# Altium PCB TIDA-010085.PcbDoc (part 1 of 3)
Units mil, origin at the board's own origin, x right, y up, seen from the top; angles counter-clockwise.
Board outline 1968.5 x 2559.06 mil, 4 copper layers (Top Layer, Signal Layer 1, Signal Layer 2, Bottom Layer), stack 5.6 mil thick; 254 components, 133 nets, 771 pads, 156 vias.
Unrouted connection lines stored in the file: 2.
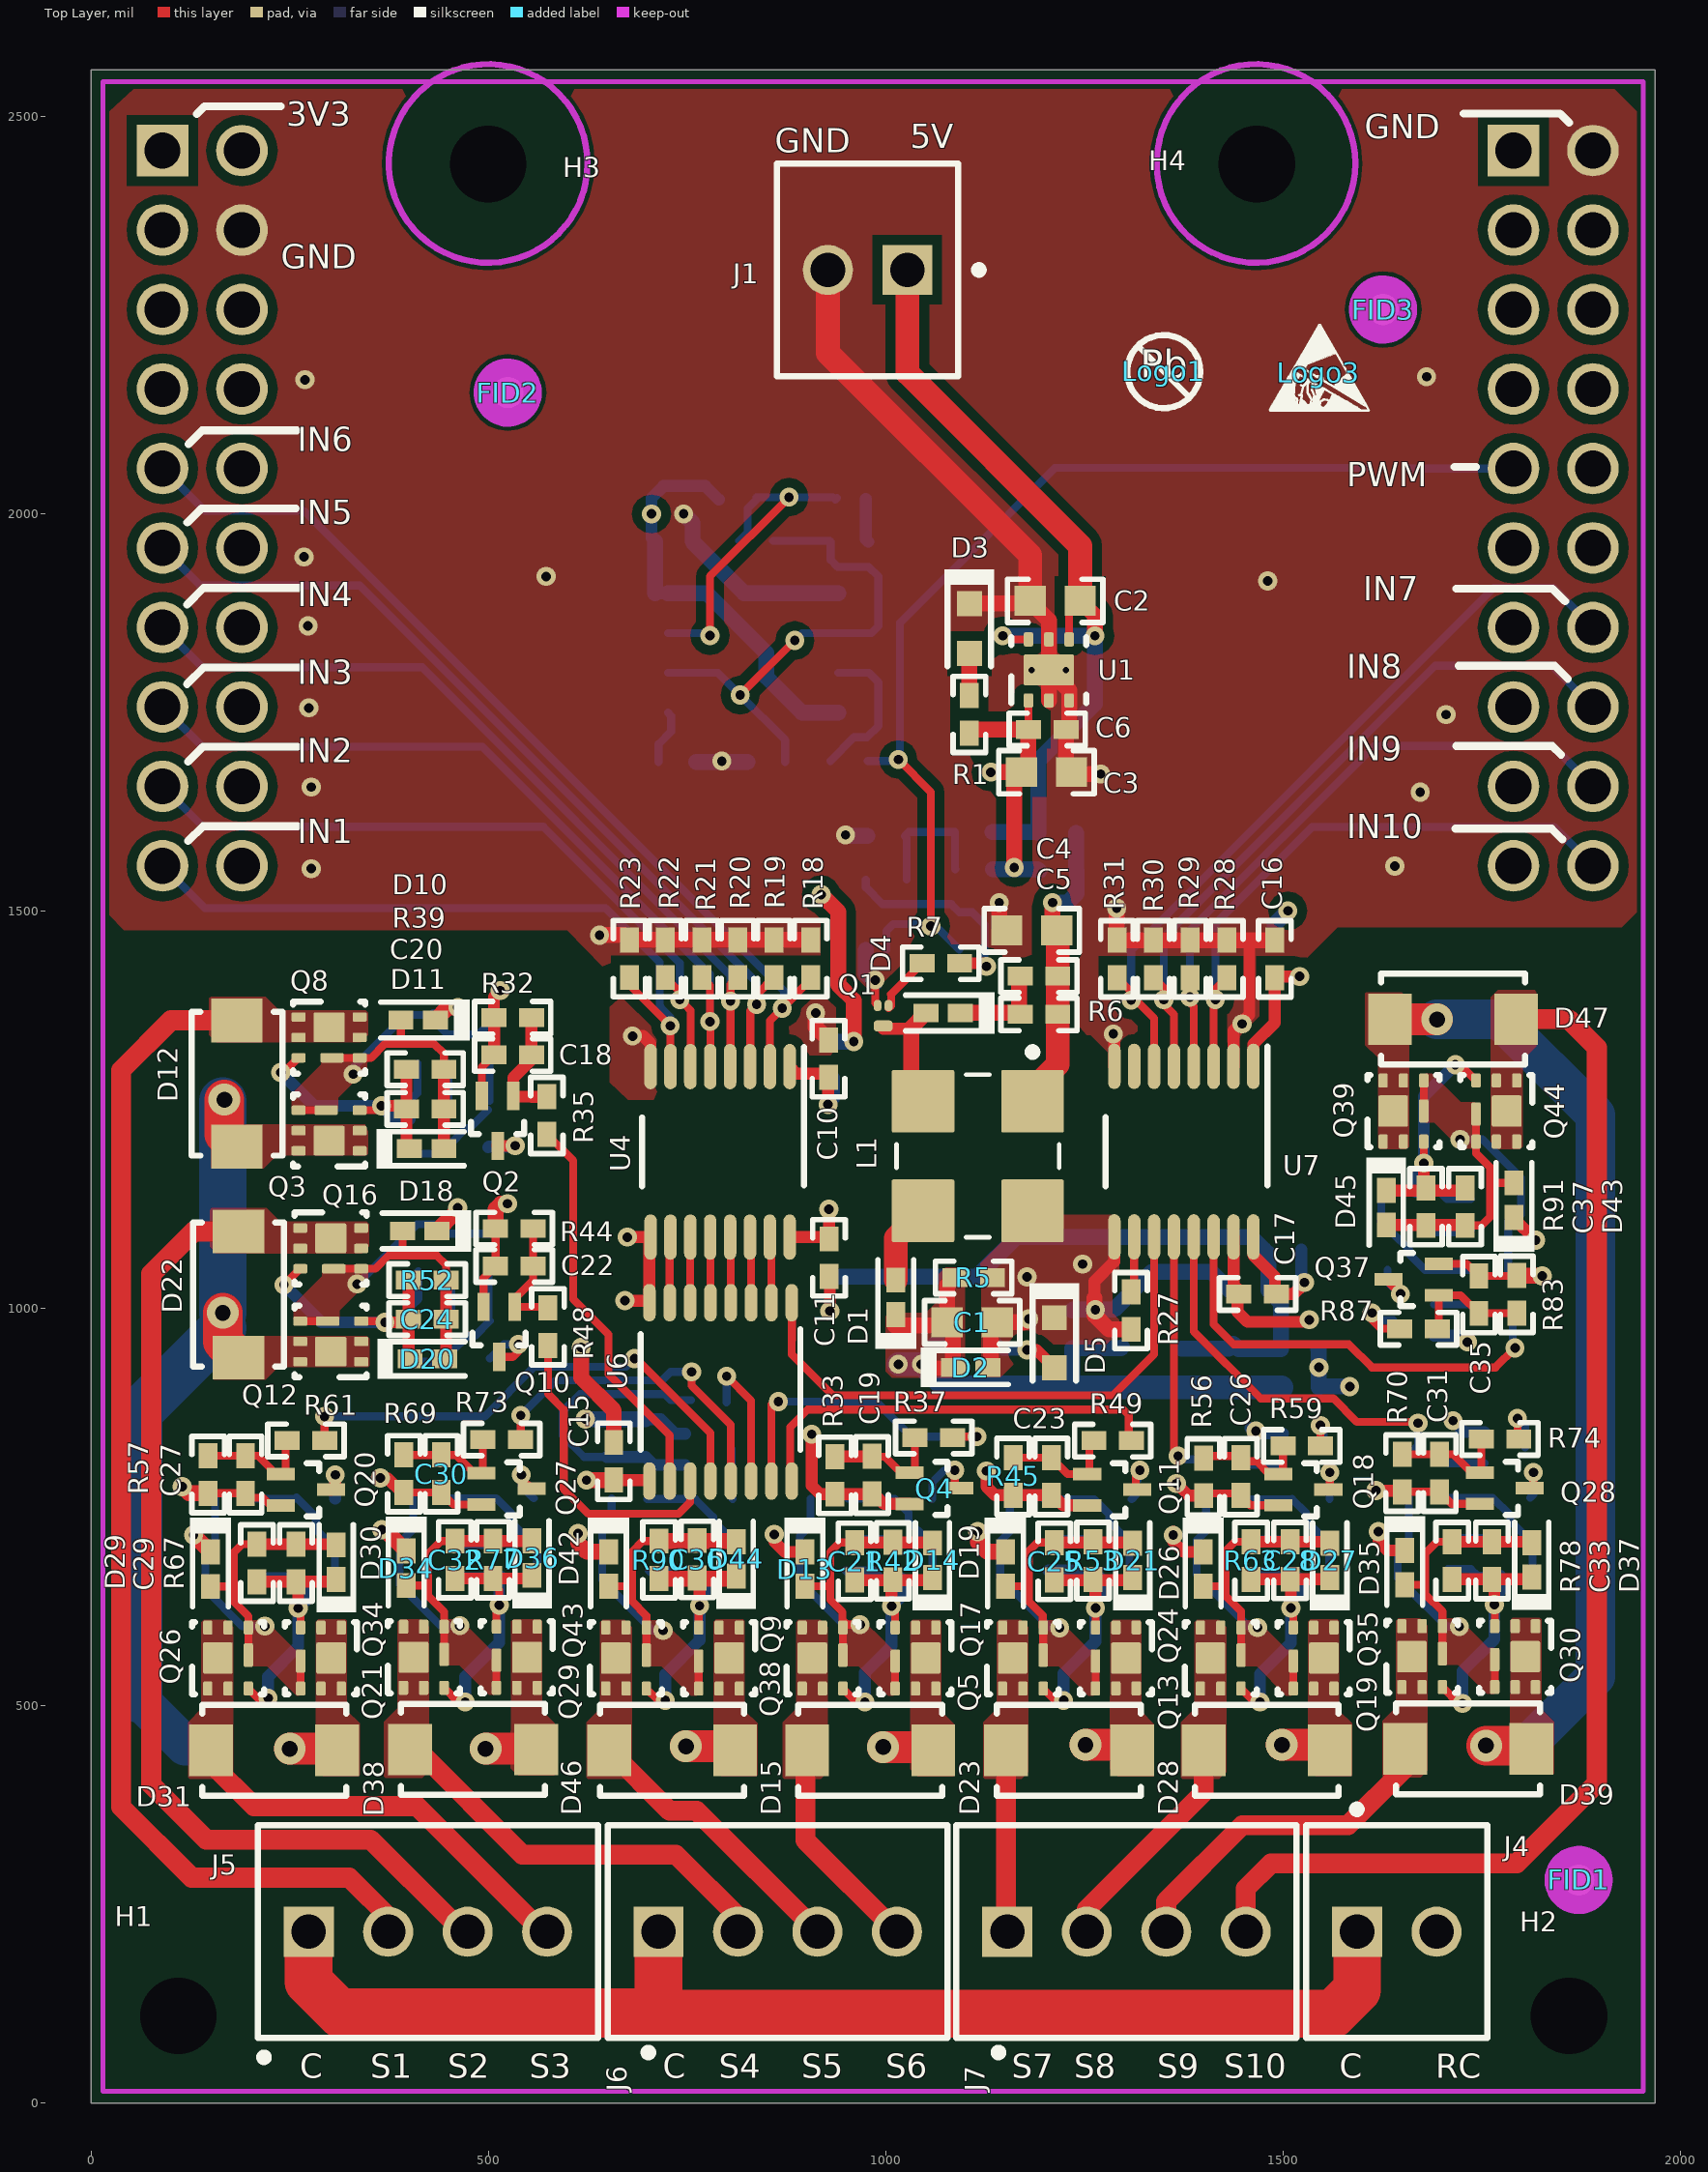
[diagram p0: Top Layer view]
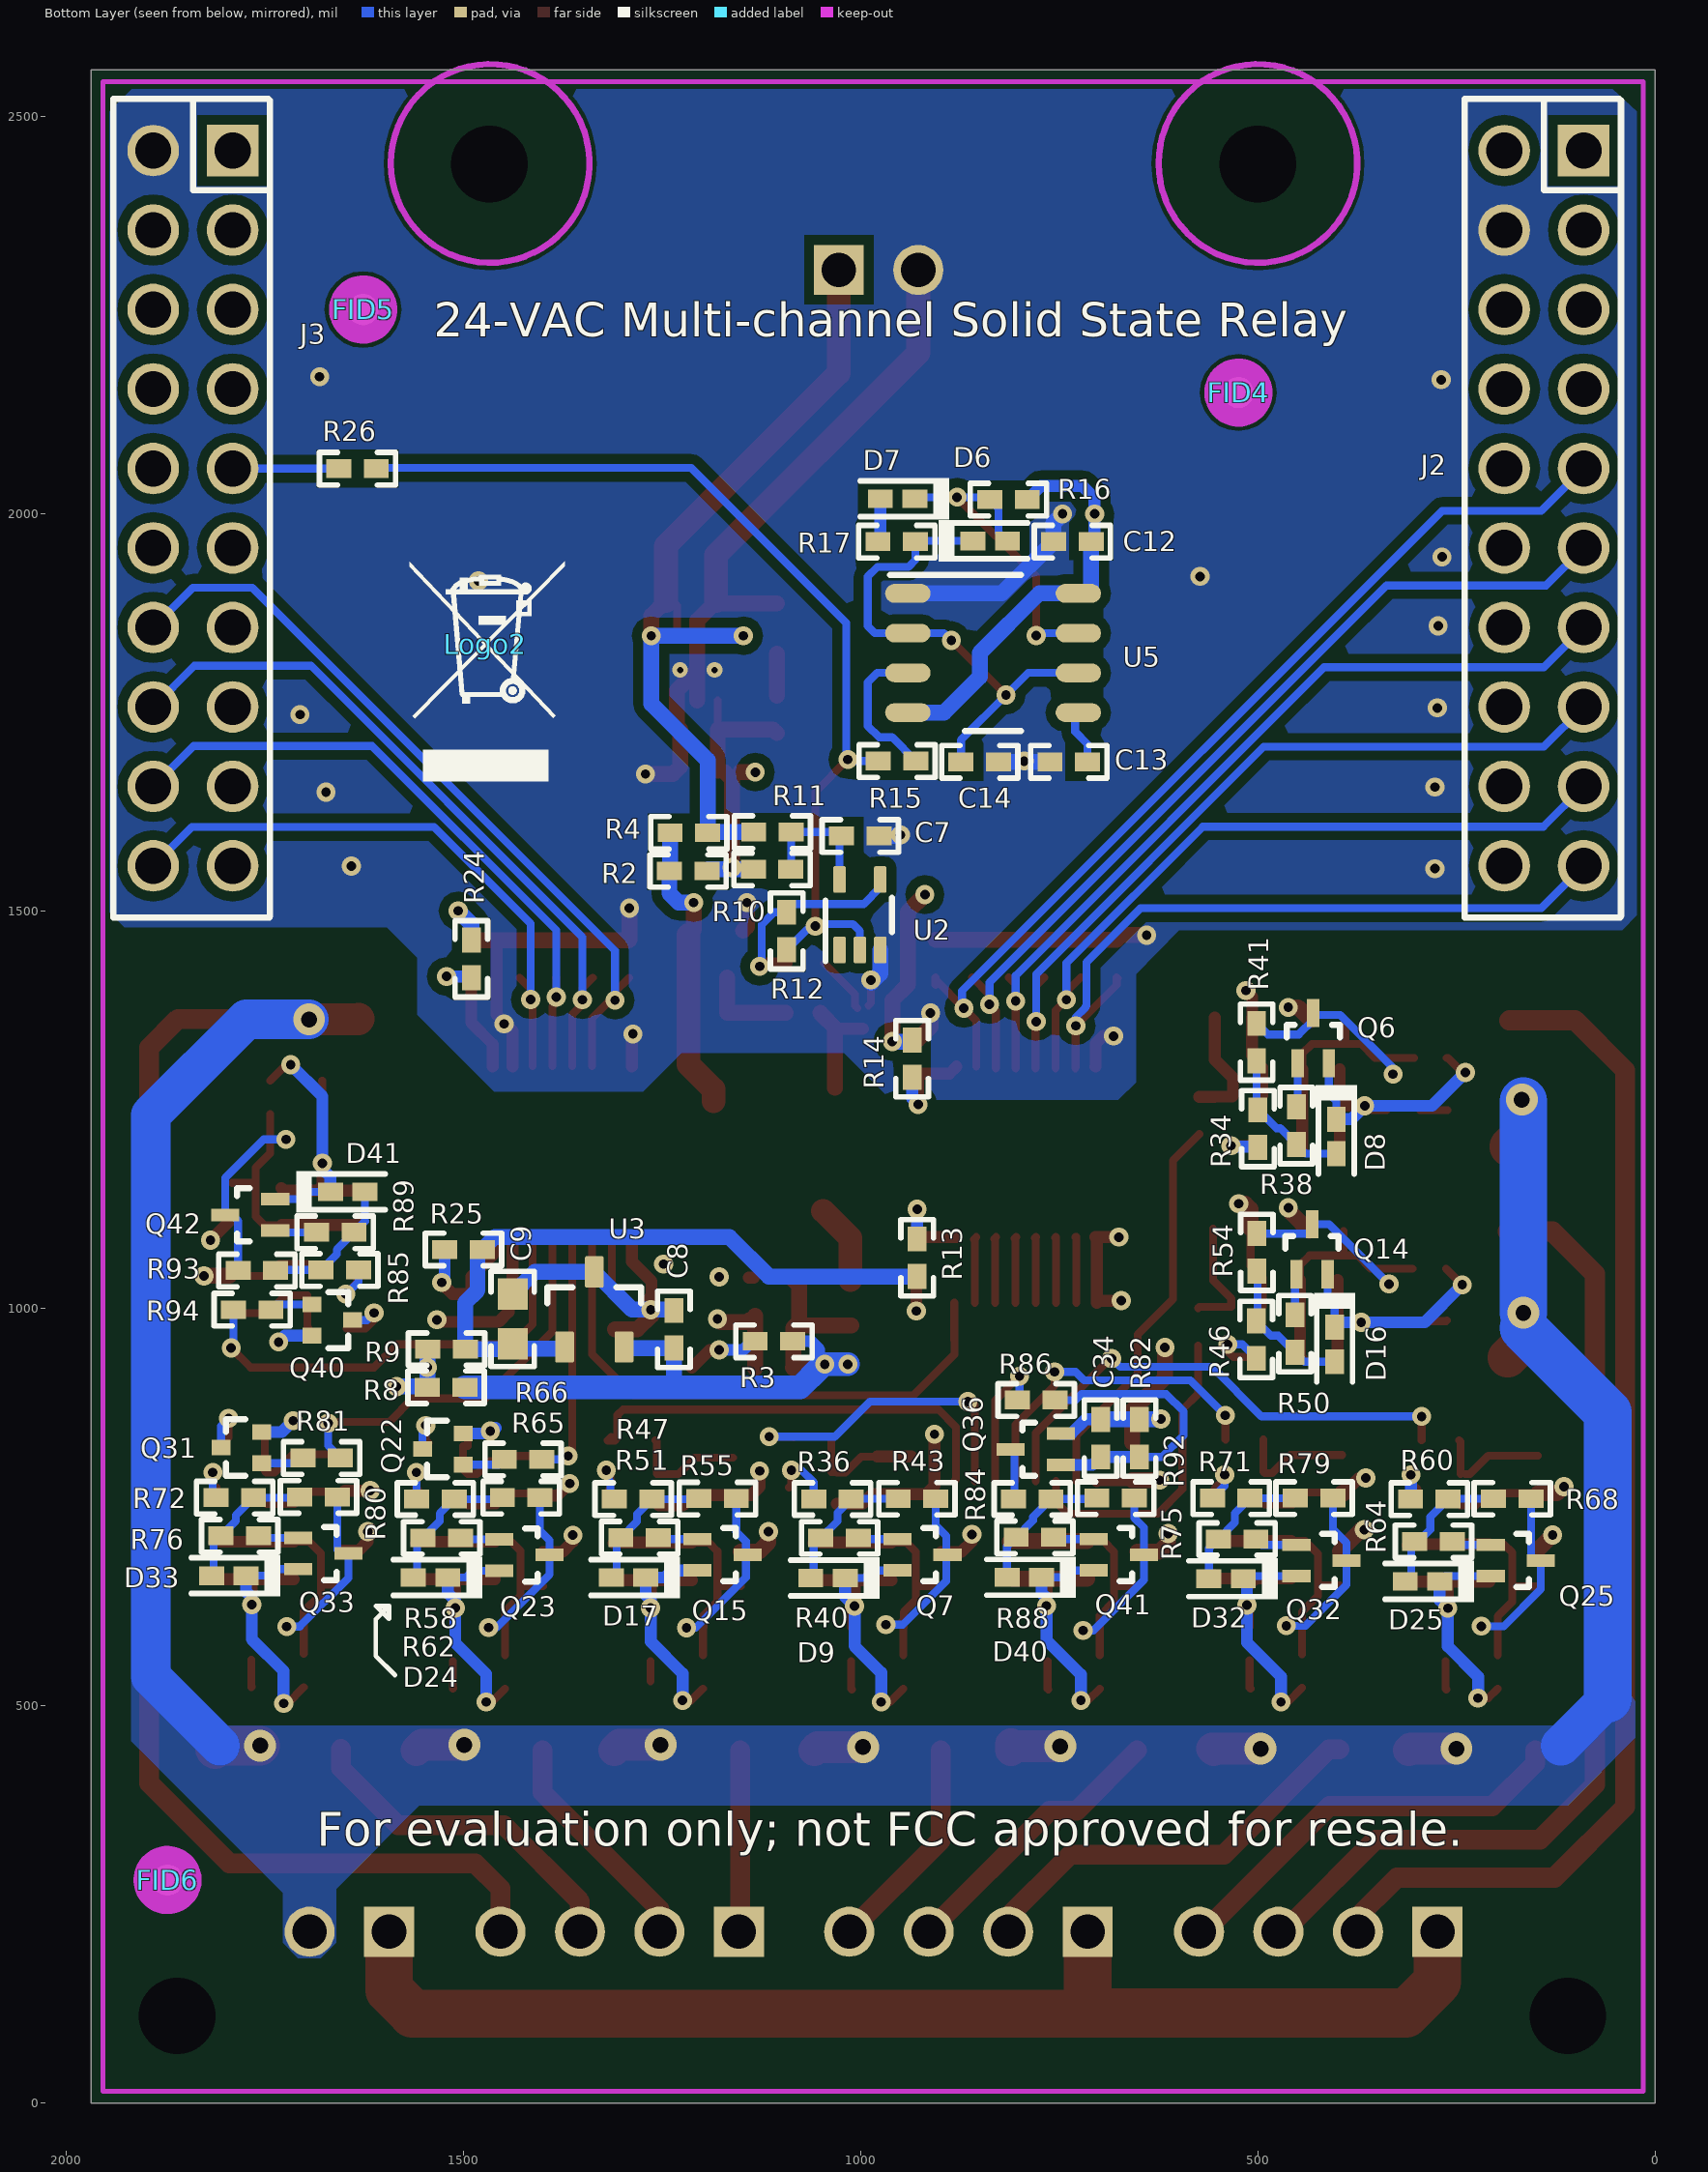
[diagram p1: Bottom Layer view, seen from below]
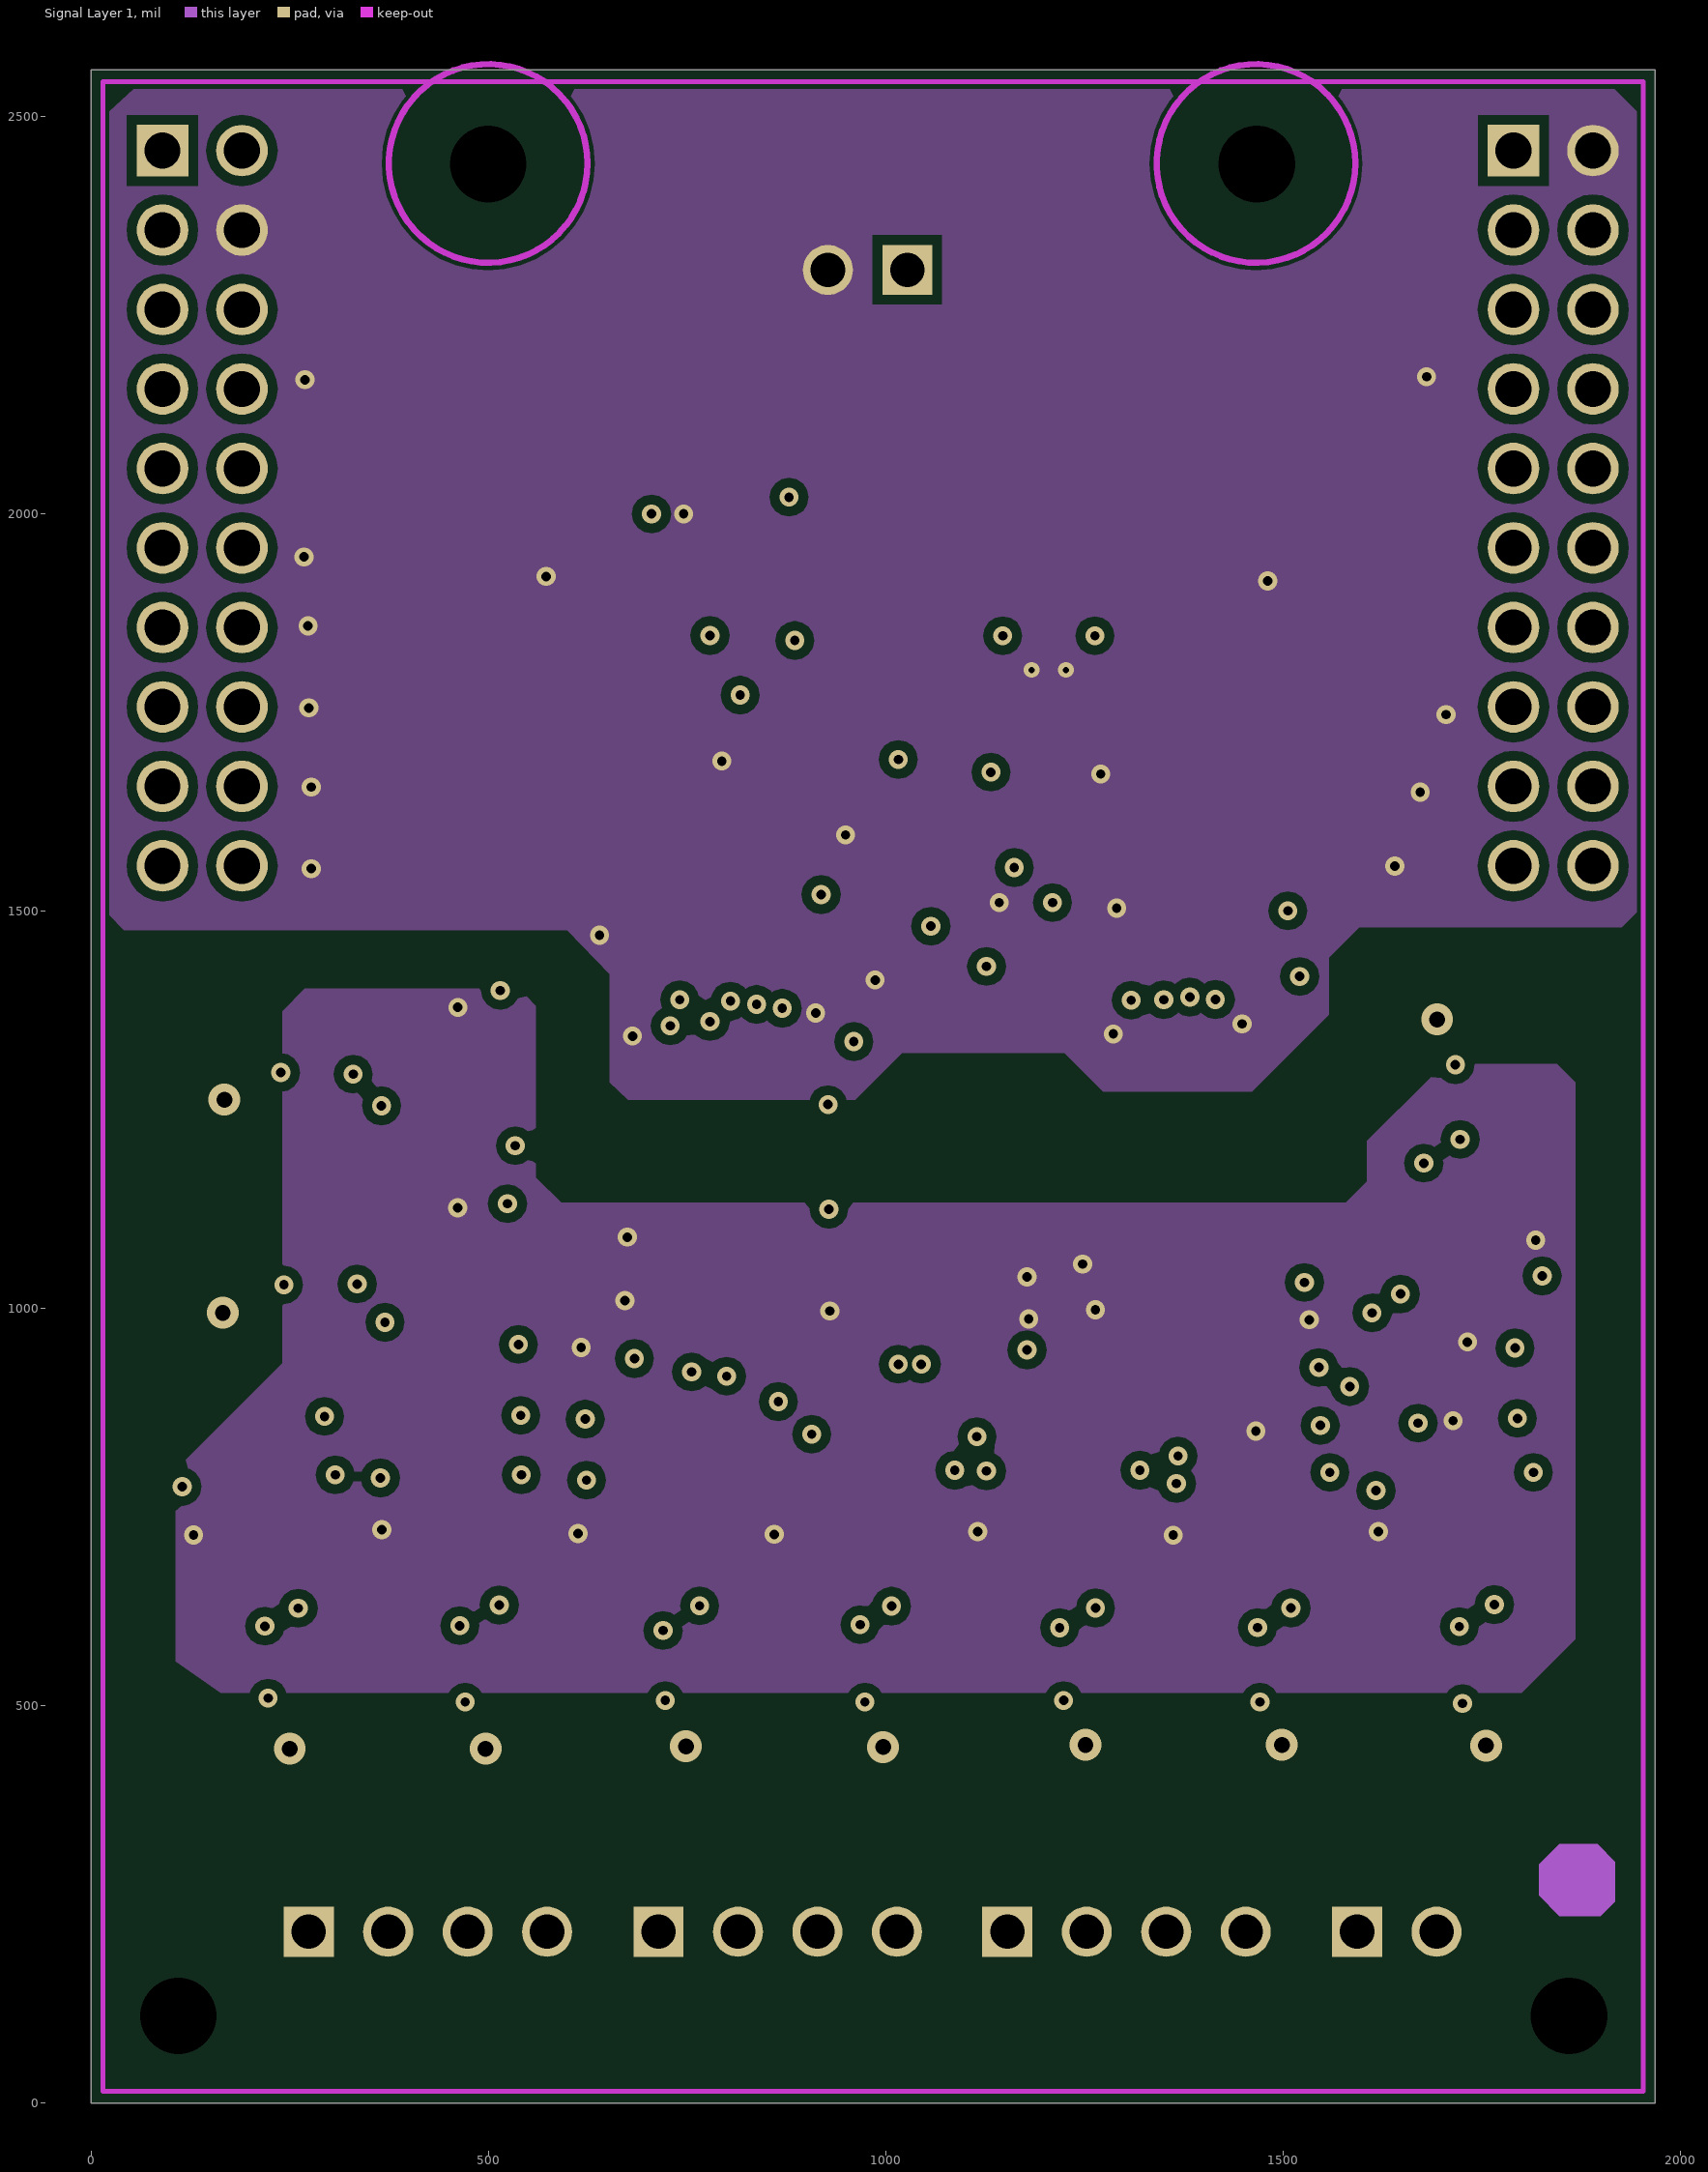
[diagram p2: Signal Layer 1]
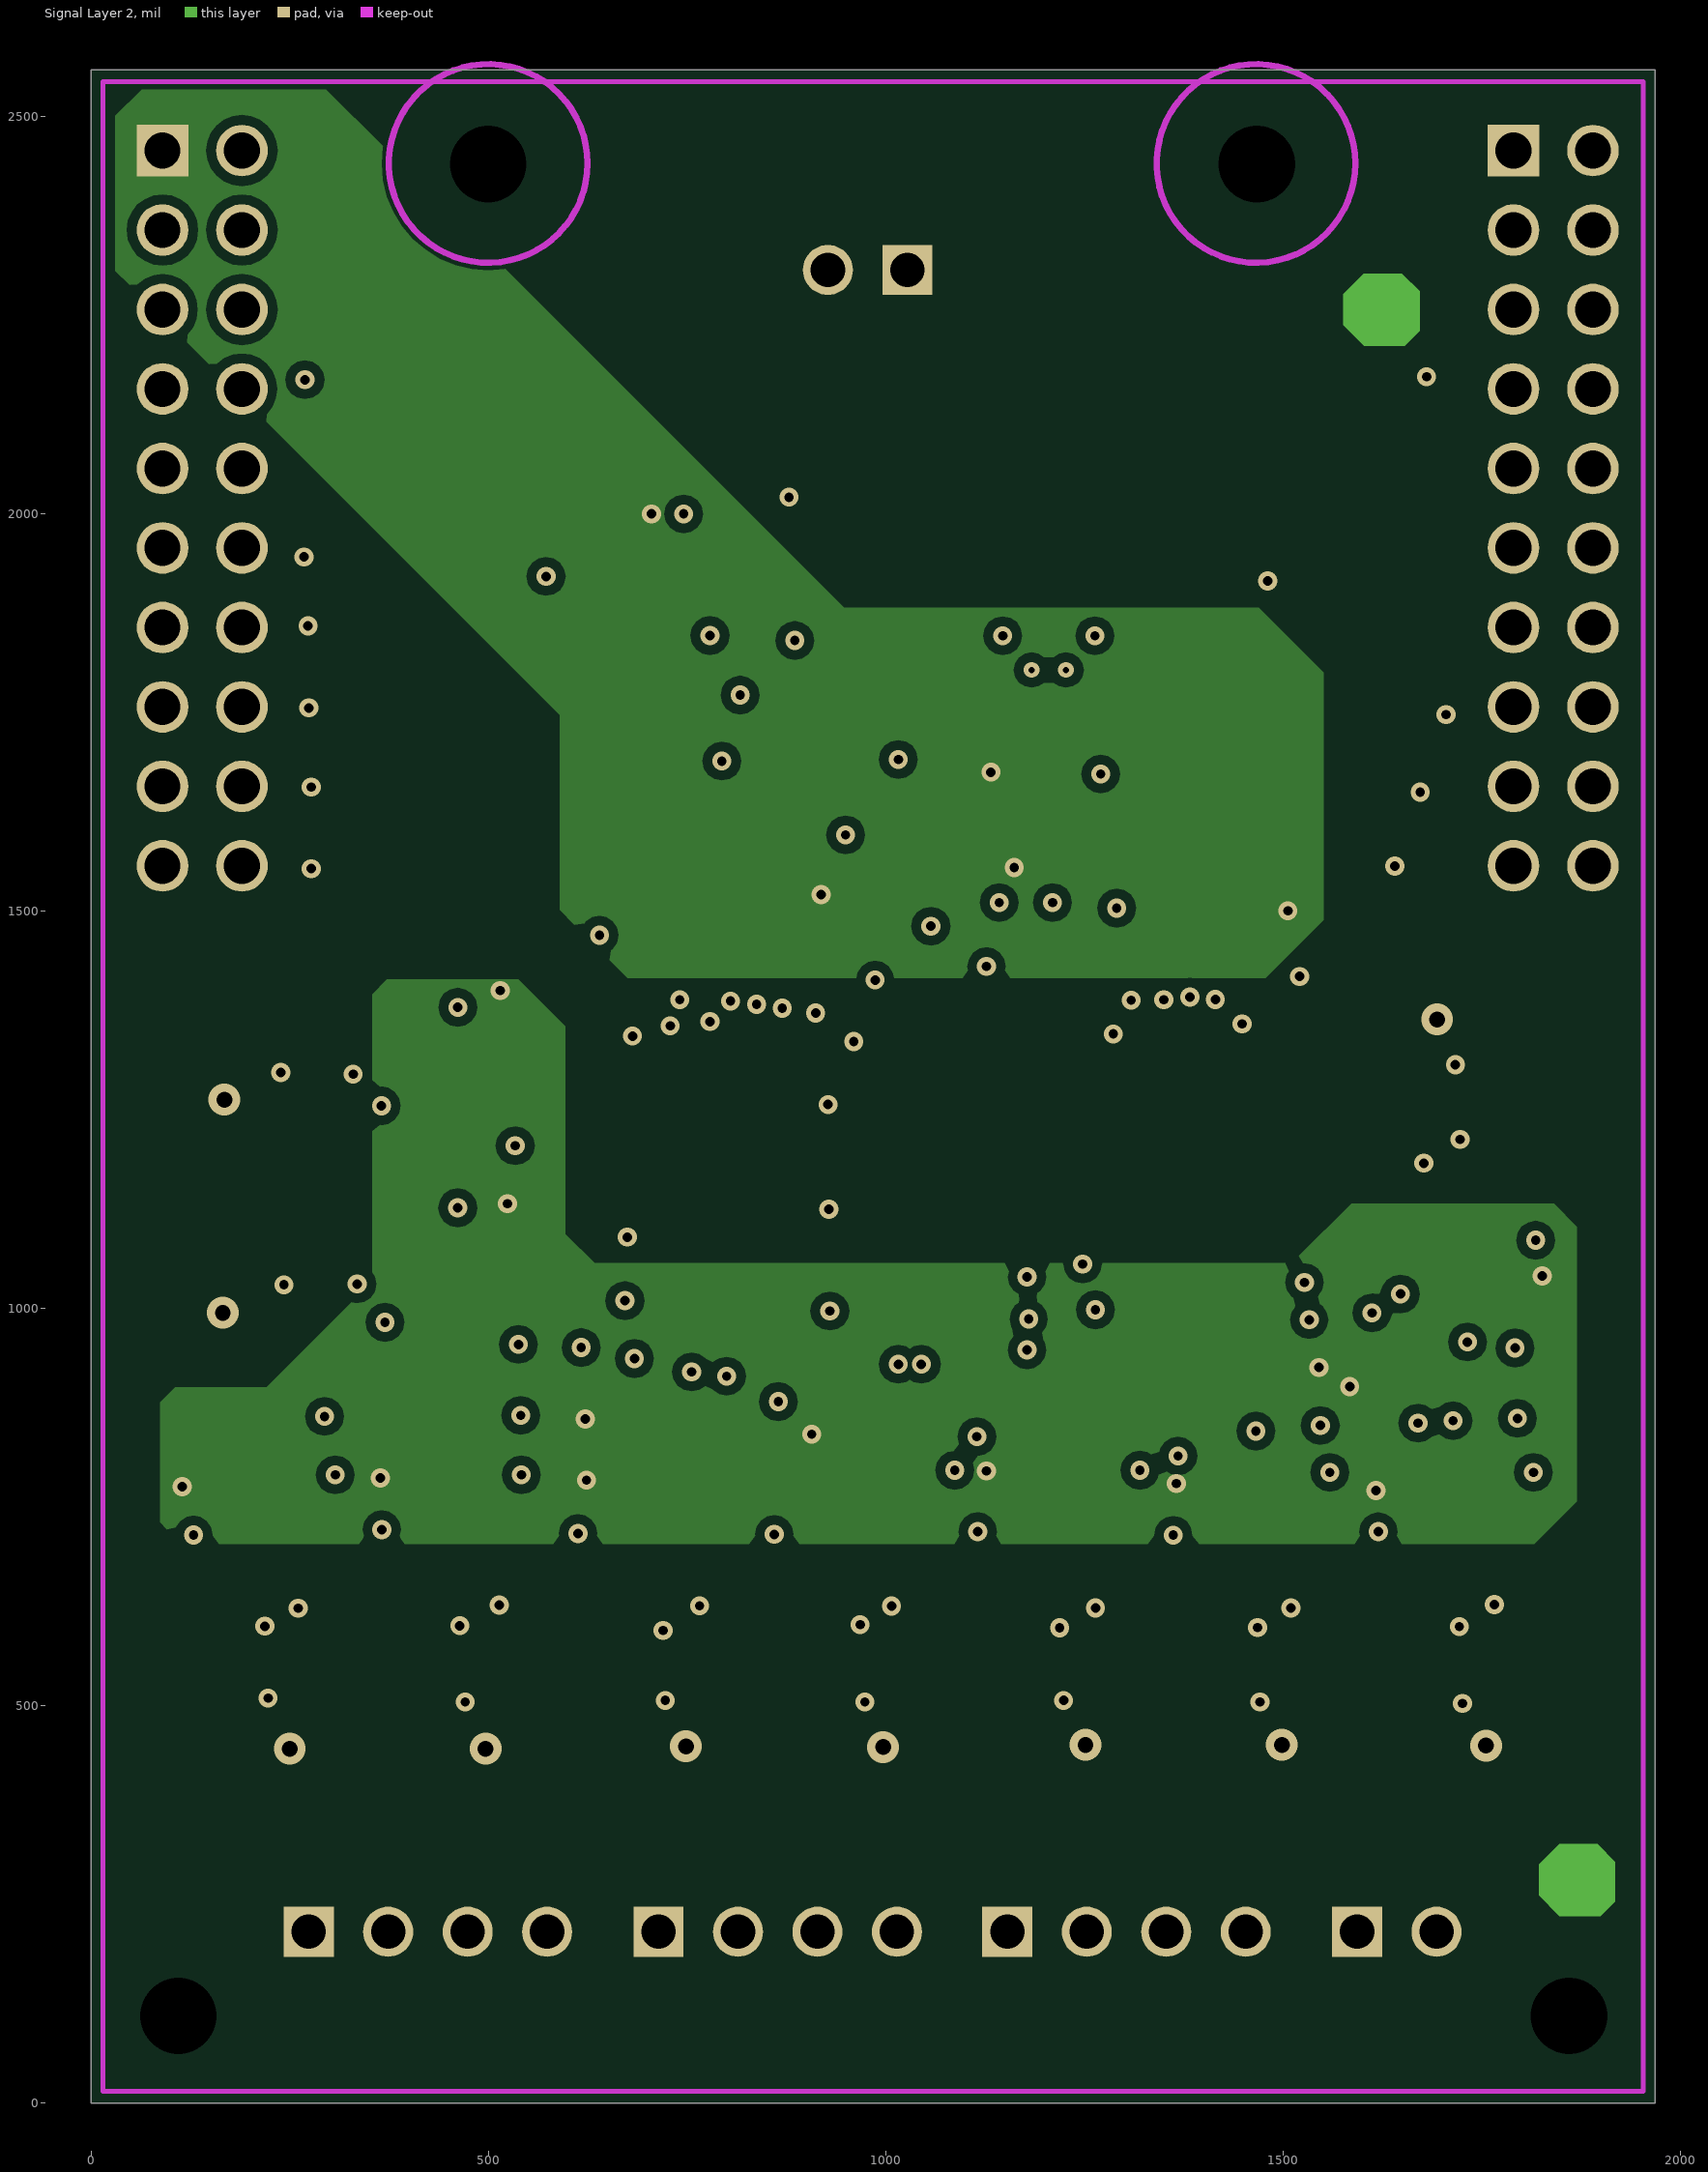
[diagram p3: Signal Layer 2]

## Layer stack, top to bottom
Top Solder: solder mask 0.4, Solder Resist, Dk 3.5
Top Layer: signal copper 1.4
Signal Layer 1: signal copper 1.4
Signal Layer 2: signal copper 1.4
Bottom Layer: signal copper 1.4
Bottom Solder: solder mask 0.4, Solder Resist, Dk 3.5

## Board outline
0,0 1968.5,0 1968.5,2559.06 0,2559.06

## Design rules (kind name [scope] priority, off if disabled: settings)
AcuteAngle [All] p1: minimum=4.50000000000000E+0001 checktracksonly=FALSE
AssemblyTestPointUsage [All] p1: valid=2
Clearance "Rooom Q1" [WithinRoom('Room Q1') vs OnTopLayer] p1: gap=3.94 ignorepadtopadclearanceinfootprint=FALSE except(0: Arc-Hole Track-Hole SMDPad-Hole THPad-Hole Via-Hole Fill-Hole Poly-Hole Region-Hole Text-Hole)
Clearance Clearance_u1 [InPadClass('U1')] p2: gap=7.7 ignorepadtopadclearanceinfootprint=FALSE except(0: Arc-Hole Track-Hole SMDPad-Hole THPad-Hole Via-Hole Fill-Hole Poly-Hole Region-Hole Text-Hole)
Clearance Clearance_Boardedge_poly [OnCopper and InPolygon vs IsKeepOut] p3: gap=5 ignorepadtopadclearanceinfootprint=FALSE except(0: Arc-Hole Track-Hole SMDPad-Hole THPad-Hole Via-Hole Fill-Hole Poly-Hole Region-Hole Text-Hole)
Clearance Clearance_MTG_COPPER [InPadClass('MTG') vs InPolygon] p4: gap=40 ignorepadtopadclearanceinfootprint=FALSE except(0: Arc-Hole Track-Hole SMDPad-Hole THPad-Hole Via-Hole Fill-Hole Poly-Hole Region-Hole Text-Hole)
Clearance "Shape to Shape" [InPolygon vs InPolygon] p5: gap=20 ignorepadtopadclearanceinfootprint=FALSE except(0: Arc-Hole Track-Hole SMDPad-Hole THPad-Hole Via-Hole Fill-Hole Poly-Hole Region-Hole Text-Hole)
Clearance "shape to all" [InPolygon] p6: gap=12 ignorepadtopadclearanceinfootprint=FALSE except(0: Arc-Hole Track-Hole SMDPad-Hole THPad-Hole Via-Hole Fill-Hole Poly-Hole Region-Hole Text-Hole)
Clearance "Clearance_via_thr pin" [IsVia vs IsThruPin] p7: gap=8 ignorepadtopadclearanceinfootprint=FALSE except(0: Arc-Hole Track-Hole SMDPad-Hole THPad-Hole Via-Hole Fill-Hole Poly-Hole Region-Hole Text-Hole)
Clearance [All] p8: gap=7 ignorepadtopadclearanceinfootprint=FALSE except(0: Arc-Hole Track-Hole SMDPad-Hole THPad-Hole Via-Hole Fill-Hole Poly-Hole Region-Hole Text-Hole)
DiffPairsRouting DiffPair_DiffPairsRouting [InDifferentialPair ('kan')] p1: maxlimit=10 minlimit=10 mostfreqgap=10 toplayer_minwidth=15 toplayer_maxwidth=15 toplayer_prefwidth=15 midlayer1_minwidth=15 midlayer1_maxwidth=15 midlayer1_prefwidth=15 midlayer2_minwidth=15 midlayer2_maxwidth=15 midlayer2_prefwidth=15 bottomlayer_minwidth=15 bottomlayer_maxwidth=15 bottomlayer_prefwidth=15 maxuncoupledlength=500
DiffPairsRouting DiffPair_DiffPairsRouting_1 [InDifferentialPair ('kan')] p2: maxlimit=10 minlimit=10 mostfreqgap=10 toplayer_minwidth=15 toplayer_maxwidth=15 toplayer_prefwidth=15 midlayer1_minwidth=15 midlayer1_maxwidth=15 midlayer1_prefwidth=15 midlayer2_minwidth=15 midlayer2_maxwidth=15 midlayer2_prefwidth=15 bottomlayer_minwidth=15 bottomlayer_maxwidth=15 bottomlayer_prefwidth=15 maxuncoupledlength=500
DiffPairsRouting [All] p3: maxlimit=100 minlimit=10 mostfreqgap=10 toplayer_minwidth=15 toplayer_maxwidth=15 toplayer_prefwidth=15 midlayer1_minwidth=15 midlayer1_maxwidth=15 midlayer1_prefwidth=15 midlayer2_minwidth=15 midlayer2_maxwidth=15 midlayer2_prefwidth=15 bottomlayer_minwidth=15 bottomlayer_maxwidth=15 bottomlayer_prefwidth=15 maxuncoupledlength=1000
FabricationTestPointUsage TestPointUsage [All] p1: valid=2 allowmultiple=FALSE
FabricationTestpoint Testpoint [All] p1: side=3 testpointundercomponent=TRUE minsize=40 maxsize=100 preferedsize=60 minholesize=0 maxholesize=40 preferedholesize=32 testpointgrid=1 allowsidetop=TRUE allowsidebottom=TRUE usegrid=TRUE gridtolerance=0.01
FanoutControl Fanout_LCC [IsLCC] p1: bgadir=Out bgaviamode=Centered fanoutstyle=Auto fanoutdirection=Alternating viagrid=1 // Fanout_LCC (Default Rule)
FanoutControl Fanout_BGA [IsBGA] p2: bgadir=Out bgaviamode=Centered fanoutstyle=Auto fanoutdirection=Alternating viagrid=1 // Fanout_BGA (Default Rule)
FanoutControl Fanout_Default [All] p4: bgadir=Out bgaviamode=Centered fanoutstyle=Auto fanoutdirection=Alternating viagrid=1 // Fanout_Default (Default Rule)
FanoutControl Fanout_Small [(CompPinCount < 5)] p5: bgadir=Out bgaviamode=Centered fanoutstyle=Auto fanoutdirection=OutThenIn viagrid=1 // Fanout_Small (Default Rule)
HoleSize [All] p1: absolutevalues=TRUE maxlimit=1000 minlimit=7 maxpercent=80.000 minpercent=20.000
MatchedLengths DiffPair_MatchedLengths [InDifferentialPair ('kan')] p1: tolerance=1000 checknetsindiffpair=TRUE checkdiffpairvsdiffpair=FALSE checkxsignals=FALSE checkothers=FALSE
MatchedLengths DiffPair_MatchedLengths_1 [InDifferentialPair ('kan')] p2: tolerance=1000 checknetsindiffpair=TRUE checkdiffpairvsdiffpair=FALSE checkxsignals=FALSE checkothers=FALSE
MinimumAnnularRing [All] p1: minimumring=5
MinimumAnnularRing MinimumAnnularRing_ThermalPadVias [IsVia and InAnyComponent] p2: minimumring=5.91
MinimumSolderMaskSliver MinimumSolderMaskSliver_Logo [InComponentClass('Logo') vs InComponentClass('Logo')] p1: minsoldermaskwidth=0.7
MinimumSolderMaskSliver [All] p2: minsoldermaskwidth=3.94
PlaneClearance [All] p1: clearance=15
PolygonConnect [All] p1: connectstyle=Direct reliefconductorwidth=10 reliefentries=4 polygonreliefangle="90 Angle" airgapwidth=10
RoomDefinition "Room Q1" [False] p1: confinementstyle=ConfineIn formatcopy=TRUE lockcomponents=FALSE outline 979.82,1397.94 1013,1397.94 1013,1344 979.82,1344
RoutingVias RoutingVias_power [InNetClass('POWER')] p1: holewidth=16 width=32 viastyle="Through Hole" minholewidth=7.87 minwidth=19.68 maxholewidth=16 maxwidth=32
RoutingVias ThermalPadVias [IsVia and InAnyComponent] p2: holewidth=8 width=20 viastyle="Through Hole" minholewidth=7.87 minwidth=19 maxholewidth=12 maxwidth=24
RoutingVias [All] p3: holewidth=10 width=20 viastyle="Through Hole" minholewidth=7.87 minwidth=19.68 maxholewidth=30 maxwidth=60
SMDToCorner [All] p1: distance=30000
SilkToSilkClearance [All] p1: silktosilkclearance=5
SilkToSolderMaskClearance SilkscreenOverComponentPads [IsPad] p1: minsilkscreentomaskgap=0 clearancetoexposedcopper=TRUE
SolderMaskExpansion [All] p1: expansion=3
Width Width_power [InNetClass('pwr')] p1: maxlimit=200 minlimit=10 preferedwidth=20
Width [All] p2: maxlimit=100 minlimit=6 preferedwidth=8 checkconnectedcopper=TRUE
17 further rules are at their usual default settings.

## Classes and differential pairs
component class TIDA-010085_Page2: C18 C19 C20 C21 C22 C23 C24 C25 C26 C27 C28 C29 C30 C31 C32 C33 C34 C35 C36 C37 D8 D9 D10 D11 D12 D13 D14 D15 D16 D17 D18 D19 D20 D21 D22 D23 D24 D25 D26 D27 D28 D29 D30 D31 D32 D33 D34 D35 D36 D37 D38 D39 D40 D41 D42 D43 D44 D45 D46 D47 J4 J5 J6 J7 Q2 Q3 Q4 Q5 Q6 Q7 Q8 Q9 Q10 Q11 Q12 Q13 Q14 Q15 Q16 Q17 Q18 Q19 Q20 Q21 Q22 Q23 Q24 Q25 Q26 Q27 Q28 Q29 Q30 Q31 Q32 Q33 Q34 Q35 Q36 Q37 Q38 Q39 Q40 Q41 Q42 Q43 Q44 Q45 Q46 Q48 Q50 Q51 Q? R32 R33 R34 R35 R36 R37 R38 R39 R40 R41 R42 R43 R44 R45 R46 R47 R48 R49 R50 R51 R52 R53 R54 R55 R56 R57 R58 R59 R60 R61 R62 R63 R64 R65 R66 R67 R68 R69 R70 R71 R72 R73 R74 R75 R76 R77 R78 R79 R80 R81 R82 R83 R84 R85 R86 R87 R88 R89 R90 R91 R92 R93 R94
component class TIDA-010085_Page1: C1 C2 C3 C4 C5 C6 C7 C8 C9 C10 C11 C12 C13 C14 C15 C16 C17 D1 D2 D3 D4 D5 D6 D7 J1 J2 J3 L1 Q1 R1 R2 R3 R4 R5 R6 R7 R8 R9 R10 R11 R12 R13 R14 R15 R16 R17 R18 R19 R20 R21 R22 R23 R24 R25 R26 R27 R28 R29 R30 R31 S? U1 U2 U3 U4 U5 U6 U7
component class TIDA-010085_Hardware: !PCB1 H1 H2 H3 H4 Logo1 Logo2 Logo3 ZZ1 ZZ2 ZZ3 ZZ4
component class AssemblyNote: ZZ1 ZZ2 ZZ3 ZZ4

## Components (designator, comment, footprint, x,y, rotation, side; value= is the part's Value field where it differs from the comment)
C1 "GRM188R61E106MA73D" 0603 1109,982.8 r180 top value=10uF
C2 "GRM188R61A106KE69D" 0603 1213.38,1890.68 r180 top value=10uF
C3 "GRM188R61A106KE69D" 0603 1202.41,1675 r0 top value=10uF
C4 "GRM188R61A106KE69D" 0603 1184,1476 r180 top value=10uF
C5 "885012205061" 0402 1193,1418.29 r180 top value=1000pF
C6 "GCM155R71A104KA55D" 0402 1203.38,1728.68 r0 top value=0.1uF
C7 "GCM155R71A104KA55D" 0402 1000.35,1594.61 r180 bottom value=0.1uF
C8 "GRM155R71H104ME14D" 0402 1235,974 r90 bottom value=0.1uF
C9 "GRM188R61A106KE69D" 0603 1437.61,987 r90 bottom value=10uF
C10 "GCM155R71A104KA55D" 0402 928.2,1314.47 r270 top value=0.1uF
C11 "GCM155R71A104KA55D" 0402 928.73,1064 r270 top value=0.1uF
C12 "GCM155R71A104KA55D" 0402 733.51,1965 r180 bottom value=0.1uF
C13 "GCM155R71A104KA55D" 0402 738,1688 r0 bottom value=0.1uF
C14 "GRT155R71H471KE01D" 0402 850,1688 r180 bottom value=470pF
C15 "GRM155R71H104ME14D" 0402 658,808 r90 top value=0.1uF
C16 "GCM155R71A104KA55D" 0402 1489.83,1440.12 r270 top value=0.1uF
C17 "GCM155R71A104KA55D" 0402 1468,1018.49 r180 top value=0.1uF
C18 "885012205061" 0402 530.78,1319.12 r0 top value=1000pF
C19 "885012205061" 0402 982.86,790.55 r90 top value=1000pF
C20 "885012205061" 0402 420.65,1251.3 r0 top value=1000pF
C21 "885012205061" 0402 961,682 r90 top value=1000pF
C22 "885012205061" 0402 532.83,1053.73 r0 top value=1000pF
C23 "885012205061" 0402 1208.56,788.79 r90 top value=1000pF
C24 "885012205061" 0402 423.35,986.8 r0 top value=1000pF
C25 "885012205061" 0402 1212.3,682 r90 top value=1000pF
C26 "885012205061" 0402 1447,788.62 r90 top value=1000pF
C27 "885012205061" 0402 194.58,791.29 r90 top value=1000pF
C28 "885012205061" 0402 1509,683.13 r90 top value=1000pF
C29 "885012205061" 0402 208.98,680 r90 top value=1000pF
C30 "885012205061" 0402 440.94,792.29 r90 top value=1000pF
C31 "885012205061" 0402 1697.11,793.11 r90 top value=1000pF
C32 "885012205061" 0402 458,684 r90 top value=1000pF
C33 "885012205061" 0402 1763,683 r90 top value=1000pF
C34 "885012205061" 0402 698,837 r270 bottom value=1000pF
C35 "885012205061" 0402 1746.57,1017.61 r270 top value=1000pF
C36 "885012205061" 0402 763,684.5 r90 top value=1000pF
C37 "885012205061" 0402 1729,1128.27 r270 top value=1000pF
D1 "RB520S30,115" SOD-523 1013,1014.35 r90 top value=30V
D2 "BZT585B12T-7" SOD-523 1107,925.98 r0 top value=12V
D3 "150060RS75000" WL-SMCW_RED 1105.38,1855.68 r270 top value=Red
D4 "RB520S30,115" SOD-523 1072.35,1372 r180 top value=30V
D5 "150060RS75000" WL-SMCW_RED 1212.3,957 r270 top value=Red
D6 "RB520S30,115" SOD-523 836.86,1966 r180 bottom value=30V
D7 "RB520S30,115" SOD-523 953.51,2019 r0 bottom value=30V
D8 "BAS516,115" SOD-523 401.29,1216.65 r270 bottom value=100V
D9 "BAS516,115" SOD-523 1041,661 r0 bottom value=100V
D10 "BAS516,115" SOD-523 411.78,1363.12 r180 top value=100V
D11 "BZT585B12T-7" SOD-523 422.65,1201.3 r0 top value=12V
D12 "SMAJ40CA" SMA_Bi 183.78,1283.12 r270 top value=40V
D13 "BAS516,115" SOD-523 898.65,672.29 r270 top value=100V
D14 "BZT585B12T-7" SOD-523 1059,683.5 r90 top value=12V
D15 "SMAJ40CA" SMA_Bi 980.65,444.29 r0 top value=40V
D16 "BAS516,115" SOD-523 403.35,954.8 r270 bottom value=100V
D17 "BAS516,115" SOD-523 1292,661.63 r0 bottom value=100V
D18 "BAS516,115" SOD-523 413.83,1097.73 r180 top value=100V
D19 "BAS516,115" SOD-523 1150.76,672.29 r270 top value=100V
D20 "BZT585B12T-7" SOD-523 423.35,936.8 r0 top value=12V
D21 "BZT585B12T-7" SOD-523 1311,683.13 r90 top value=12V
D22 "SMAJ40CA" SMA_Bi 185.83,1017.73 r270 top value=40V
D23 "SMAJ40CA" SMA_Bi 1230.76,444.29 r0 top value=40V
D24 "BAS516,115" SOD-523 1541,661.63 r0 bottom value=100V
D25 "BAS516,115" SOD-523 293,656.82 r0 bottom value=100V
D26 "BAS516,115" SOD-523 1399.65,672.29 r270 top value=100V
D27 "BZT585B12T-7" SOD-523 1559,683.13 r90 top value=12V
D28 "SMAJ40CA" SMA_Bi 1479.65,444.29 r0 top value=40V
D29 "BAS516,115" SOD-523 150.58,672 r270 top value=100V
D30 "BZT585B12T-7" SOD-523 308.82,681 r90 top value=12V
D31 "SMAJ40CA" SMA_Bi 230.58,444.29 r0 top value=40V
D32 "BAS516,115" SOD-523 540,660 r0 bottom value=100V
D33 "BAS516,115" SOD-523 1795,664 r0 bottom value=100V
D34 "BAS516,115" SOD-523 396.94,673.29 r270 top value=100V
D35 "BAS516,115" SOD-523 1653.11,674.11 r270 top value=100V
D36 "BZT585B12T-7" SOD-523 555,686 r90 top value=12V
D37 "BZT585B12T-7" SOD-523 1813,684 r90 top value=12V
D38 "SMAJ40CA" SMA_Bi 480.94,445.29 r0 top value=40V
D39 "SMAJ40CA" SMA_Bi 1733.11,446.11 r0 top value=40V
D40 "BAS516,115" SOD-523 794,662 r0 bottom value=100V
D41 "BAS516,115" SOD-523 1645.35,1147 r180 bottom value=100V
D42 "BAS516,115" SOD-523 651.4,672.29 r270 top value=100V
D43 "BAS516,115" SOD-523 1790.57,1136.61 r90 top value=100V
D44 "BZT585B12T-7" SOD-523 812,685 r90 top value=12V
D45 "BZT585B12T-7" SOD-523 1630,1127 r270 top value=12V
D46 "SMAJ40CA" SMA_Bi 731.4,444.29 r0 top value=40V
D47 "SMAJ40CA" SMA_Bi 1714,1364.23 r180 top value=40V
FID1 "CMP-0077181-1" Fiducial10-20 1872,281 r0 top
FID2 "CMP-0077181-1" Fiducial10-20 524.64,2152.65 r0 top (schematic designator FID1)
FID3 "CMP-0077181-1" Fiducial10-20 1625.98,2257.17 r0 top (schematic designator FID1)
FID4 "CMP-0077181-1" Fiducial10-20 524.64,2152.65 r180 bottom (schematic designator FID1)
FID5 "CMP-0077181-1" Fiducial10-20 1625.98,2257.17 r180 bottom (schematic designator FID1)
FID6 "CMP-0077181-1" Fiducial10-20 1872,281 r180 bottom (schematic designator FID1)
H1 "NY PMS 256 0025 PH" "NY PMS 256 0025 PH" 110,110 r0 top
H2 "NY PMS 256 0025 PH" "NY PMS 256 0025 PH" 1860,110 r0 top
H3 "NY PMS 256 0025 PH" "NY PMS 256 0025 PH" 500,2440 r0 top
H4 "NY PMS 256 0025 PH" "NY PMS 256 0025 PH" 1467,2440 r0 top
J1 "282834-2" TEC_282834-2 977.39,2307 r180 top
J2 "SSW-110-23-F-D" CONN_SSW-110-23-F-D 140.08,2007.17 r90 bottom
J3 "SSW-110-23-F-D" CONN_SSW-110-23-F-D 1840.08,2007.17 r90 bottom
J4 "282834-2" TEC_282834-2 1643.27,216 r0 top
J5 "282834-4" TEC_282834-4 424.13,216 r0 top
J6 "282834-4" TEC_282834-4 864.24,216 r0 top
J7 "282834-4" TEC_282834-4 1303.13,216 r0 top
L1 "744889030330" FP-744889020330_SMD4-MFG 1116,1192 r270 top
Logo1 "Pb-Free Symbol" Pb-Free_Overlay_Small 1350,2179 r0 top
Logo2 "WEEE logo" WEEE_Minimum 1471.89,1836 r180 bottom
Logo3 "ESD Susceptible" ESD_Overlay_Small 1545,2178 r0 top
Q1 "CSD17382F4" FP-CSD17382F4_PICOSTAR3-MFG 996.86,1368.56 r270 top
Q2 "MMBT2907AT-7-F" SOT-523 511.78,1236.12 r270 top value="60 V"
Q3 "CSD19538Q2" DQK0006C#1 299.78,1224.12 r180 top value=100V
Q4 "MMBT2907AT-7-F" SOT-523 1061.47,773.95 r0 top value="60 V"
Q5 "CSD19538Q2" DQK0006C#1 1037.65,560.29 r270 top value=100V
Q6 "MMBT2907AT-7-F" SOT-523 430.43,1340.3 r90 bottom value="60 V"
Q7 "MMBT2907AT-7-F" SOT-523 922,690.29 r180 bottom value="60 V"
Q8 "CSD19538Q2" DQK0006C#1 299.78,1341.12 r0 top value=100V
Q9 "CSD19538Q2" DQK0006C#1 920.65,560.29 r90 top value=100V
Q10 "MMBT2907AT-7-F" SOT-523 513.83,970.73 r270 top value="60 V"
Q11 "MMBT2907AT-7-F" SOT-523 1285.18,772.08 r0 top value="60 V"
Q12 "CSD19538Q2" DQK0006C#1 301.83,958.73 r180 top value=100V
Q13 "CSD19538Q2" DQK0006C#1 1289.76,560.29 r270 top value=100V
Q14 "MMBT2907AT-7-F" SOT-523 431.83,1074.8 r90 bottom value="60 V"
Q15 "MMBT2907AT-7-F" SOT-523 1173.64,690.31 r180 bottom value="60 V"
Q16 "CSD19538Q2" DQK0006C#1 301.83,1075.73 r0 top value=100V
Q17 "CSD19538Q2" DQK0006C#1 1172.76,560.29 r90 top value=100V
Q18 "MMBT2907AT-7-F" SOT-523 1525.65,772.29 r0 top value="60 V"
Q19 "CSD19538Q2" DQK0006C#1 1538.65,560.29 r270 top value=100V
Q20 "MMBT2907AT-7-F" SOT-523 270.58,772.1 r0 top value="60 V"
Q21 "CSD19538Q2" DQK0006C#1 289.58,560.29 r270 top value=100V
Q22 "NSVBC846BM3T5G" SOT-416 1525.65,823.29 r0 bottom value=65V
Q23 "MMBT2907AT-7-F" SOT-523 1423,690 r180 bottom value="60 V"
Q24 "CSD19538Q2" DQK0006C#1 1421.65,560.29 r90 top value=100V
Q25 "MMBT2907AT-7-F" SOT-523 175.5,683 r180 bottom value="60 V"
Q26 "CSD19538Q2" DQK0006C#1 172.58,560.29 r90 top value=100V
Q27 "MMBT2907AT-7-F" SOT-523 522.94,773.29 r0 top value="60 V"
Q28 "MMBT2907AT-7-F" SOT-523 1779.11,774.11 r0 top value="60 V"
Q29 "CSD19538Q2" DQK0006C#1 535.94,561.29 r270 top value=100V
Q30 "CSD19538Q2" DQK0006C#1 1792.11,562.11 r270 top value=100V
Q31 "NSVBC846BM3T5G" SOT-416 1779.11,825.11 r0 bottom value=65V
Q32 "MMBT2907AT-7-F" SOT-523 420,683 r180 bottom value="60 V"
Q33 "MMBT2907AT-7-F" SOT-523 1676,692 r180 bottom value="60 V"
Q34 "CSD19538Q2" DQK0006C#1 418.94,561.29 r90 top value=100V
Q35 "CSD19538Q2" DQK0006C#1 1675.11,562.11 r90 top value=100V
Q36 "MMBT2907AT-7-F" SOT-523 779.55,823 r0 bottom value="60 V"
Q37 "MMBT2907AT-7-F" SOT-523 1664.57,1036.61 r180 top value="60 V"
Q38 "CSD19538Q2" DQK0006C#1 790.4,560.29 r270 top value=100V
Q39 "CSD19538Q2" DQK0006C#2 1651.57,1248.61 r90 top value=100V
Q40 "NSVBC846BM3T5G" SOT-416 1664.57,985.61 r180 bottom value=65V
Q41 "MMBT2907AT-7-F" SOT-523 675,690.29 r180 bottom value="60 V"
Q42 "MMBT2907AT-7-F" SOT-523 1768,1118 r0 bottom value="60 V"
Q43 "CSD19538Q2" DQK0006C#1 673.4,560.29 r90 top value=100V
Q44 "CSD19538Q2" DQK0006C#1 1768.57,1248.61 r270 top value=100V
R1 "CRCW04023K30JNED" 0402 1105.38,1747.68 r270 top value=3.3k
R2 "RC0402JR-070RL" 0402 1216.97,1550.76 r0 bottom value=0
R3 "RMCF0402FT10K0" 0402 1109,959 r180 bottom value=10.0k
R4 "RC0402JR-070RL" 0402 1216.07,1598.76 r0 bottom value=0
R5 "RMCF0402FT10K0" 0402 1110.86,1039.12 r0 top value=10.0k
R6 "RMCF0402FT10K0" 0402 1193,1370.29 r0 top value=10.0k
R7 "RC0402FR-07100RL" 0402 1069.47,1434.6 r180 top value=100
R8 "RC0402JR-070RL" 0402 1521.53,901 r0 bottom value=0
R9 "RC0402JR-070RL" 0402 1521,949 r180 bottom value=0
R10 "RC0402JR-070RL" 0402 1111.35,1552.82 r180 bottom value=0
R11 "RC0402JR-070RL" 0402 1110.86,1599.67 r180 bottom value=0
R12 "RC0402JR-070RL" 0402 1092.98,1475.15 r90 bottom value=0
R13 "RC0402JR-070RL" 0402 928.73,1064 r270 bottom value=0
R14 "RC0402JR-070RL" 0402 935,1314.47 r90 bottom value=0
R15 "RC0402JR-070RL" 0402 954,1689 r0 bottom value=0
R16 "CRCW04022K87FKED" 0402 813.89,2018 r180 bottom value=2.87k
R17 "CRCW04027K50FKED" 0402 954.51,1965 r180 bottom value=7.50k
R18 "ERJ-2RKF1003X" 0402 905.75,1440.34 r270 top value=100k
R19 "ERJ-2RKF1003X" 0402 859.56,1440.34 r270 top value=100k
R20 "ERJ-2RKF1003X" 0402 813.75,1440.34 r270 top value=100k
R21 "ERJ-2RKF1003X" 0402 768.75,1440.34 r270 top value=100k
R22 "ERJ-2RKF1003X" 0402 722.75,1440.34 r270 top value=100k
R23 "ERJ-2RKF1003X" 0402 677.75,1440.34 r270 top value=100k
R24 "RC0402JR-070RL" 0402 1489.83,1440.12 r90 bottom value=0
R25 "RC0402JR-070RL" 0402 1499.64,1074.38 r180 bottom value=0
R26 "RC0402JR-070RL" 0402 1633,2057 r180 bottom value=0
R27 "RC0402FR-074K7L" 0402 1308.93,997.54 r270 top value=4.70k
R28 "ERJ-2RKF1003X" 0402 1429.2,1440.12 r270 top value=100k
R29 "ERJ-2RKF1003X" 0402 1383.2,1440.12 r270 top value=100k
R30 "ERJ-2RKF1003X" 0402 1336.99,1440.12 r270 top value=100k
R31 "ERJ-2RKF1003X" 0402 1291.2,1440.12 r270 top value=100k
R32 "RMCF0402FT10K0" 0402 530.78,1366.12 r180 top value=10.0k
R33 "RMCF0402FT10K0" 0402 936.33,790.22 r270 top value=10.0k
R34 "CRCW0402475RFKED" 0402 499.96,1226.46 r90 bottom value=475
R35 "ERJ-2RKF1003X" 0402 573.78,1243.12 r90 top value=100k
R36 "CRCW0402475RFKED" 0402 1035.31,760.47 r180 bottom value=475
R37 "ERJ-2RKF1003X" 0402 1060.58,837.88 r180 top value=100k
R38 "RC0402JR-070RL" 0402 451.65,1230.3 r270 bottom value=0
R39 "RMCF0402FT10K0" 0402 420.65,1301.3 r180 top value=10.0k
R40 "RC0402JR-070RL" 0402 1026.38,711.52 r0 bottom value=0
R41 "ERJ-2RKF1003X" 0402 501.65,1335.3 r270 bottom value=100k
R42 "RMCF0402FT10K0" 0402 1009,682.5 r270 top value=10.0k
R43 "ERJ-2RKF1003X" 0402 929,760.77 r0 bottom value=100k
R44 "RMCF0402FT10K0" 0402 532.83,1100.73 r180 top value=10.0k
R45 "RMCF0402FT10K0" 0402 1160.56,788.79 r270 top value=10.0k
R46 "CRCW0402475RFKED" 0402 502.01,961.07 r90 bottom value=475
R47 "CRCW0402475RFKED" 0402 1286.14,760.29 r180 bottom value=475
R48 "ERJ-2RKF1003X" 0402 575.19,977.15 r90 top value=100k
R49 "ERJ-2RKF1003X" 0402 1285.76,834 r180 top value=100k
R50 "RC0402JR-070RL" 0402 453.35,968.52 r270 bottom value=0
R51 "RC0402JR-070RL" 0402 1278,711.68 r0 bottom value=0
R52 "RMCF0402FT10K0" 0402 423.35,1035.8 r180 top value=10.0k
R53 "RMCF0402FT10K0" 0402 1261,683 r270 top value=10.0k
R54 "ERJ-2RKF1003X" 0402 501.35,1070.8 r270 bottom value=100k
R55 "ERJ-2RKF1003X" 0402 1180,761 r0 bottom value=100k
R56 "RMCF0402FT10K0" 0402 1400,788.31 r270 top value=10.0k
R57 "RMCF0402FT10K0" 0402 147.58,791.29 r270 top value=10.0k
R58 "CRCW0402475RFKED" 0402 1535.03,760.47 r180 bottom value=475
R59 "ERJ-2RKF1003X" 0402 1523.7,827.23 r180 top value=100k
R60 "CRCW0402475RFKED" 0402 284.36,760.29 r180 bottom value=475
R61 "ERJ-2RKF1003X" 0402 270.58,834.29 r180 top value=100k
R62 "RC0402JR-070RL" 0402 1527,711.52 r0 bottom value=0
R63 "RMCF0402FT10K0" 0402 1460,683 r270 top value=10.0k
R64 "RC0402JR-070RL" 0402 279,707.12 r0 bottom value=0
R65 "ERJ-2RKF1003X" 0402 1427,762.11 r0 bottom value=100k
R66 "ERJ-2RKF1003X" 0402 1424.65,810.29 r0 bottom value=100k
R67 "RMCF0402FT10K0" 0402 257.9,680 r270 top value=10.0k
R68 "ERJ-2RKF1003X" 0402 180,760.77 r0 bottom value=100k
R69 "RMCF0402FT10K0" 0402 393.94,792.29 r270 top value=10.0k
R70 "RMCF0402FT10K0" 0402 1650.11,793.11 r270 top value=10.0k
R71 "CRCW0402475RFKED" 0402 533.6,761.47 r180 bottom value=475
R72 "CRCW0402475RFKED" 0402 1787.49,762.11 r180 bottom value=475
R73 "ERJ-2RKF1003X" 0402 516.94,835.29 r180 top value=100k
R74 "ERJ-2RKF1003X" 0402 1773.11,836.11 r180 top value=100k
R75 "RC0402JR-070RL" 0402 526.16,710 r0 bottom value=0
R76 "RC0402JR-070RL" 0402 1781.11,714.11 r0 bottom value=0
R77 "RMCF0402FT10K0" 0402 506,684 r270 top value=10.0k
R78 "RMCF0402FT10K0" 0402 1713,683 r270 top value=10.0k
R79 "ERJ-2RKF1003X" 0402 429.36,761.47 r0 bottom value=100k
R80 "ERJ-2RKF1003X" 0402 1682,763 r0 bottom value=100k
R81 "ERJ-2RKF1003X" 0402 1678.11,812.11 r0 bottom value=100k
R82 "RMCF0402FT10K0" 0402 649,837 r90 bottom value=10.0k
R83 "RMCF0402FT10K0" 0402 1794.16,1017.92 r90 top value=10.0k
R84 "CRCW0402475RFKED" 0402 784,760.47 r180 bottom value=475
R85 "CRCW0402475RFKED" 0402 1655.19,1048.61 r0 bottom value=475
R86 "ERJ-2RKF1003X" 0402 779,885 r180 bottom value=100k
R87 "ERJ-2RKF1003X" 0402 1670.57,974.61 r0 top value=100k
R88 "RC0402JR-070RL" 0402 780.61,712.29 r0 bottom value=0
R89 "RC0402JR-070RL" 0402 1661,1096 r180 bottom value=0
R90 "RMCF0402FT10K0" 0402 715,684 r270 top value=10.0k
R91 "RMCF0402FT10K0" 0402 1680,1128.27 r90 top value=10.0k
R92 "ERJ-2RKF1003X" 0402 679,761.47 r0 bottom value=100k
R93 "ERJ-2RKF1003X" 0402 1759.62,1048 r180 bottom value=100k
R94 "ERJ-2RKF1003X" 0402 1765.57,998.61 r180 bottom value=100k
U1 "TLV75533PDRVR" DRV0006A 1205.38,1803.68 r90 top
U2 "SN74LV1T34DCKR" DCK0005A_N 1000.84,1495.61 r90 bottom
U3 "TLV76050DBZR" DBZ0003A_N 1335,999 r90 bottom
U4 "ISO7760FDBQR" DBQ0016A_N 791.8,1197.29 r270 top
U5 "TLC555CD" D0008A_N 833.28,1825 r180 bottom
U6 "TPL7407LPWR" PW0016A_L 792.35,895.26 r270 top
U7 "ISO7740FDBQR" DBQ0016A_N 1375.28,1197.54 r270 top
ZZ1 "This Assembly Note is for PCB labels only" AssemblyNoteLabel -1454,2999 r0 top
ZZ2 "These assemblies are ESD sensitive, ESD precautions shall be observed." AssemblyNote -1460.15,2936.85 r0 top
ZZ3 "These assemblies must be clean and free from flux and all contaminants. Use of no clean flux is not acceptable." AssemblyNote -1460.15,2861.85 r0 top
ZZ4 "These assemblies must comply with workmanship standards IPC-A-610 Class 2, unless otherwise specified." AssemblyNote -1458.15,2790.85 r90 top

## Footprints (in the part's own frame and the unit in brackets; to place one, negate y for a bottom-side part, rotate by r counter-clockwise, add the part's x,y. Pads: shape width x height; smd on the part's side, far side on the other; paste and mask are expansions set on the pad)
0402 [mm] "0402 from SM-752 data"
  rect 0.8x0.6 smd mask+0.05: 1(-0.6,0) 2(0.6,0)
  silkscreen extent -1.22,-0.52 1.22,0.52, body extent -0.55,-0.3 0.55,0.3, height 0.6
0603 [mm] "0603 from SM-752 data"
  rect 1x0.95 smd mask+0.05: 1(-0.8,0) 2(0.8,0)
  silkscreen extent -1.52,-0.69 1.52,0.69, body extent -0.87,-0.47 0.87,0.47, height 1
AssemblyNote [mil] "Assembly Note"
AssemblyNoteLabel [mil] "Assembly Note for PCB Labels"
CONN_SSW-110-23-F-D [mm] "SAMTEC"
  rect 1.65x1.65 hole 1.15 mask+0.05: 1(11.43,-1.27)
  round 1.65 hole 1.15 mask+0.05: 2(11.43,1.27) 3(8.89,-1.27) 4(8.89,1.27) 5(6.35,-1.27) 6(6.35,1.27) 7(3.81,-1.27) 8(3.81,1.27) 9(1.27,-1.27) 10(1.27,1.27) 11(-1.27,-1.27) 12(-1.27,1.27) 13(-3.81,-1.27) 14(-3.81,1.27) 15(-6.35,-1.27) 16(-6.35,1.27) 17(-8.89,-1.27) 18(-8.89,1.27) 19(-11.43,-1.27) 20(-11.43,1.27)
  silkscreen extent -13.08,-2.46 13.08,2.54, body extent -13,-2.51 13,2.54, height 8.59
D0008A_N [mm] "SOIC, 8-Leads, Body 4.9x3.9mm, Pitch 1.27mm, IPC Medium Density"
  oval 1.45x0.6 smd mask+0.05: 1(-2.725,1.905) 2(-2.725,0.635) 3(-2.725,-0.635) 4(-2.725,-1.905) 5(2.725,-1.905) 6(2.725,-0.635) 7(2.725,0.635) 8(2.725,1.905)
  silkscreen extent -3.3,-2.5 0.9,2.5, body extent -3,-2.45 3,2.45, height 1.63
DBQ0016A_N [mm] "SOP, 16-Leads, Body 4.9x3.9mm, Pitch 0.635mm, IPC Medium Density"
  oval 1.45x0.4 smd mask+0.05: 1(-2.725,2.222) 2(-2.725,1.587) 3(-2.725,0.952) 4(-2.725,0.317) 5(-2.725,-0.318) 6(-2.725,-0.953) 7(-2.725,-1.588) 8(-2.725,-2.223) 9(2.725,-2.222) 10(2.725,-1.587) 11(2.725,-0.952) 12(2.725,-0.317) 13(2.725,0.318) 14(2.725,0.953) 15(2.725,1.588) 16(2.725,2.223)
  silkscreen extent -3.35,-2.5 1.1,2.68, body extent -3.01,-2.45 3.01,2.45, height 1.63
DBZ0003A_N [mm] "SOT23, 3-Leads, Body 2.9x1.3mm, Pitch 0.95mm, Lead Span 2.4mm, IPC Medium Density"
  rrect17% 1x0.6 smd mask+0.05: 1(-1.2,0.95) 2(-1.2,-0.95) 3(1.2,0)
  silkscreen extent 0.2,-1.5 0.7,1.5, body extent -1.26,-1.46 1.26,1.46, height 0.98
DCK0005A_N [mm] "SOT353, 5-Leads, Body 2x1.3mm, Pitch 0.65mm, Lead Span 2.1mm, IPC Medium Density"
  rrect25% 0.85x0.4 smd mask+0.05: 1(-1.125,0.65) 2(-1.125,0) 3(-1.125,-0.65) 4(1.125,-0.65) 5(1.125,0.65)
  silkscreen extent -1.48,-1.02 0.55,1.1, body extent -1.14,-1 1.14,1, height 0.95
DQK0006C#1 [mm] "WSON"
  rrect12% 0.9x0.86 on Top Paste mask+0.05: 0(0,0.325)
  rrect34% 0.7x0.29 on Top Paste mask+0.05: 0(0.095,-0.65)
  rrect33% 0.45x0.3 smd mask+0.05: 1(-0.975,0.65) 2(-0.975,0) 3(-0.975,-0.65) 4(0.975,-0.65) 5(0.975,0) 6(0.975,0.65)
  rrect33% 0.75x0.3 smd paste-0.15 mask+0.05: 7(0.095,-0.65)
  rrect11% 1x0.95 smd paste-0.5 mask+0.05: 8(0,0.325)
  silkscreen extent -1.15,-1.15 1.15,1.15, body extent -1,-1 1,1, height 0.82
DQK0006C#2 [mm] "WSON"
  rrect12% 0.9x0.86 on Top Paste mask+0.05: 0(0,0.325)
  rrect34% 0.7x0.29 on Top Paste mask+0.05: 0(0,-0.65)
  rrect33% 0.45x0.3 smd mask+0.05: 1(-0.975,0.65) 2(-0.975,0) 3(-0.975,-0.65) 4(0.975,-0.65) 5(0.975,0) 6(0.975,0.65)
  rrect33% 0.75x0.3 smd paste-0.15 mask+0.05: 7(0,-0.65)
  rrect11% 1x0.95 smd paste-0.5 mask+0.05: 8(0,0.325)
  silkscreen extent -1.15,-1.15 1.15,1.15, body extent -1,-1 1,1, height 0.82
DRV0006A [mm] "SON, 6-Leads, Body 2x2mm, Pitch 0.65mm, Thermal Pad 1.6x1mm, TI Recommended"
  rrect33% 0.45x0.3 smd mask+0.05: 1(-0.975,0.65) 2(-0.975,0) 3(-0.975,-0.65) 4(0.975,-0.65) 5(0.975,0) 6(0.975,0.65)
  rrect14% 1x0.7 on Top Paste mask+0.05: 7(0,0.45) 7(0,-0.45)
  rrect10% 1x1.6 smd paste-0.5 mask+0.05: 7(0,0)
  silkscreen extent -1.05,-1.2 1.05,1.2, body extent -1.05,-1.05 1.05,1.05, height 0.81
ESD_Overlay_Small [mil]
  silkscreen extent -62,-48 64,61
Fiducial10-20 [mm]
  round 1 smd mask+0.5: 1(0,0)
  Top Layer keep-out circle w1.178: c0,0 r0.5
FP-744889020330_SMD4-MFG [mm]
  rrect5% 2x2 smd paste+0 mask+0.05: 1(-1.75,1.75) 2(-1.75,-1.75) 3(1.75,-1.75) 4(1.75,1.75)
  silkscreen extent -3.45,-2.6 2.6,2.6, body extent -2.85,-2.85 2.85,2.85, height 0.25
FP-CSD17382F4_PICOSTAR3-MFG [mm]
  rrect80% 0.35x0.25 smd paste-1000 mask+0.05: 1(-0.325,0.175) 2(-0.325,-0.175)
  rrect57% 0.35x0.6 smd paste-1000 mask+0.05: 3(0.325,0)
  body extent -0.62,-0.42 0.62,0.42, height 0.25
"NY PMS 256 0025 PH" [mm] "Machine Screw Pan Phillips 2-56"
  round 2 hole 2.45 unplated mask+0.381: ""(0,0)
  body extent -2.12,-2.12 2.12,2.12, height 1.45
Pb-Free_Overlay_Small [mil]
  silkscreen extent -46,-46 46,46
PW0016A_L [mm] "TSOP, 16-Leads, Body 5x4.4mm, Pitch 0.65mm, IPC High Density"
  oval 1.2x0.4 smd mask+0.05: 1(-2.85,2.275) 2(-2.85,1.625) 3(-2.85,0.975) 4(-2.85,0.325) 5(-2.85,-0.325) 6(-2.85,-0.975) 7(-2.85,-1.625) 8(-2.85,-2.275) 9(2.85,-2.275) 10(2.85,-1.625) 11(2.85,-0.975) 12(2.85,-0.325) 13(2.85,0.325) 14(2.85,0.975) 15(2.85,1.625) 16(2.85,2.275)
  silkscreen extent -2,-2.55 1.85,2.55, body extent -3.21,-2.5 3.21,2.5, height 1
SMA_Bi [mm] "SMD, 2-Leads, Body 4.275x2.575mm"
  rect 1.4x1.64 smd mask+0.05: 1(-2.015,0) 2(2.015,0)
  silkscreen extent -2.3,-1.45 2.3,1.45, body extent -2.52,-1.45 2.52,1.45, height 2.65
SOD-523 [mm] "NXP Semiconductor recommended land pattern, nominal STEP model"
  rect 0.8x0.6 smd paste-0.05 mask+0.05: 1(-0.55,0) 2(0.55,0)
  silkscreen extent -1.65,-0.66 1.2,0.66, body extent -0.8,-0.4 0.8,0.4, height 0.72
SOT-416 [mm] "NXP recommended footprint."
  rect 0.6x0.5 smd mask+0.05: 1(-0.65,0.5) 2(-0.65,-0.5) 3(0.65,0)
  silkscreen extent -0.13,-0.9 0.5,0.9, body extent -0.8,-0.9 0.8,0.9, height 0.82
SOT-523 [mm] "From Diodes Inc datasheet component parameters"
  rect 0.9x0.4 smd mask+0.05: 1(-0.8,0.5) 2(-0.8,-0.5) 3(0.8,0)
  silkscreen extent 0.02,-0.85 0.42,0.85, body extent -0.8,-0.8 0.8,0.8, height 0.79
TEC_282834-2 [mm] "TEC"
  rect 1.6x1.6 hole 1.1 mask+0.05: 1(-1.27,0)
  round 1.6 hole 1.1 mask+0.05: 2(1.27,0)
  silkscreen extent -3.66,-3.4 2.9,3.4, body extent -2.77,-3.25 2.77,3.25, height 10.01
TEC_282834-4 [mm] "TEC"
  rect 1.6x1.6 hole 1.1 mask+0.05: 1(-3.81,0)
  round 1.6 hole 1.1 mask+0.05: 2(-1.27,0) 3(1.27,0) 4(3.81,0)
  silkscreen extent -5.44,-4.11 5.44,3.4, body extent -5.31,-3.25 5.31,3.25, height 10.02
WEEE_Minimum [mil] "WEEElie bin"
  silkscreen extent -95,-172 99,104
WL-SMCW_RED [mm] "WURTH"
  rect 0.8x0.8 smd mask+0.05: 1(-0.8,0) 2(0.8,0)
  silkscreen extent -1.9,-0.8 1.2,0.8, body extent -0.85,-0.45 0.85,0.45, height 0.8

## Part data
C1: library part CMP-0007344-5, "CAP, CERM, 10 uF, 25 V, +/- 20%, X5R, 0603", Cap_Case=0603, Manufacturer=MuRata, Supplier Part Number 1=490-7202-1-ND, TempCo=X5R, Tolerance_%=20%, Value1=Unknown, Value2=25V, ValueDisplayed=10uF
C2 C3 C4 C9: library part CMP-0085855-1, "CAP, CERM, 10 µF, 10 V,+/- 10%, X5R, 0603", Cap_Case=0603, Manufacturer=MuRata, TempCo=X5R, Tolerance_%=10%, Value2=10V, ValueDisplayed=10µF
C5 C18 C19 C20 C21 C22 C23 C24 C25 C26 C27 C28 C29 C30 C31 C32 C33 C34 C35 C36 C37: library part CMP-0006231-2, "CAP, CERM, 1000 pF, 50 V, +/- 10%, X7R, 0402", Cap_Case=0402, Manufacturer="Wurth Elektronik", Supplier Part Number 1=732-7556-1-ND, TempCo=X7R, Tolerance_%=10%, Value1=Unknown, Value2=50V, ValueDisplayed=1000pF
C6 C7 C10 C11 C12 C13 C16 C17: library part CMP-0006350-2, "CAP, CERM, 0.1 uF, 10 V, +/- 10%, X7R, AEC-Q200 Grade 1, 0402", Cap_Case=0402, Manufacturer=MuRata, Supplier Part Number 1=81-GCM155R71A104K5D, TempCo=X7R, Tolerance_%=10%, Value1=Unknown, Value2=10V, ValueDisplayed=0.1uF
C8 C15: library part CMP-0006675-2, "CAP, CERM, 0.1 uF, 50 V, +/- 20%, X7R, 0402", Cap_Case=0402, Manufacturer=MuRata, Supplier Part Number 1=490-10701-1-ND, TempCo=X7R, Tolerance_%=20%, Value1=Unknown, Value2=50V, ValueDisplayed=0.1uF
C14: library part CMP-0860801-1, "CAP, CERM, 470 pF, 50 V,+/- 10%, X7R, AEC-Q200 Grade 1, 0402", Cap_Case=0402, Manufacturer=MuRata, TempCo=X7R, Tolerance_%=10%, Value2=50V, ValueDisplayed=470pF
D1 D4 D6 D7: library part CMP-0028609-3, "Diode, Schottky, 30 V, 0.2 A, SOD-523", Manufacturer=Nexperia, Value1=0.2A, Value2=0.6V
D2 D11 D14 D20 D21 D27 D30 D36 D37 D44 D45: library part CMP-0005888-2, "DIODE ZENER 12V 350MW SOD523", Manufacturer="Diodes Inc.", Power_W=350mW, Supplier Part Number 1=BZT585B12T-7DICT-ND, Value1=0.35W
D3 D5: library part CMP-0002947-1, "LED, Red, SMD", Color=Red, Manufacturer="Wurth Elektronik", Power_TotalModule=72mW, Supplier Part Number 1=732-4978-1-ND, Value1=0.072W, Value2=2V
D8 D9 D10 D13 D16 D17 D18 D19 D24 D25 D26 D29 D32 D33 D34 D35 D40 D41 D42 D43: library part CMP-0076979-3, "Diode, Switching, 100 V, 0.25 A, SOD-523", Manufacturer=Nexperia, Value1=0.25A, Value2=1.25V
D12 D15 D22 D23 D28 D31 D38 D39 D46 D47: library part CMP-0085018-1, "Diode, TVS, Bi, 40 V, 64.5 Vc, 400 W, 6.2 A, SMA (non-polarized)", Manufacturer=Littelfuse, Value1=64.5V
FID1 FID2 FID3 FID4 FID5 FID6: "Fiducial mark.  There is nothing to buy or mount.", Manufacturer=N/A
H1 H2 H3 H4: library part CMP-0003709-1, "MACHINE SCREW PAN PHILLIPS 2-56", Manufacturer="B&F Fastener Supply", Supplier Part Number 1=H530-ND
J1 J4: library part CMP-0054974-1, "Terminal Block, 2x1, 2.54mm, TH", Manufacturer="TE Connectivity", Supplier Part Number 1=A98333-ND
J2 J3: library part CMP-0075442-1, "Connector, Receptacle, 100mil, 10x2, Gold plated, TH", Manufacturer=Samtec
J5 J6 J7: library part CMP-0054976-1, "Terminal Block, 100mil, 4X1 TH", Manufacturer="TE Connectivity"
L1: library part CMP-0090423-1, "Shielded 2 Coil Inductor Array Inductance - Connected in Series 33µH Inductance - Connected in Parallel 5.2Ohm DC Resistance (DCR) - Parallel 0.45A Nonstandard", Digikey Part Number=732-11686-1-ND, Manufacturer="Wurth Electronics", Mouser Part Number=710-744889030330, Operating Temperature Range="-40°C to +125°C"
Logo1: library part CMP-0074839-1
Logo2: library part CMP-0074769-1
Logo3: library part CMP-0074840-1, "ESD Susceptible Symbol"
Q1: library part CMP-0086436-1, "N-Channel 30V 2.3A (Ta) 500mW (Ta) Surface Mount 3-PICOSTAR", Manufacturer="Texas Instruments"
Q2 Q4 Q6 Q7 Q10 Q11 Q14 Q15 Q18 Q20 Q23 Q25 Q27 Q28 Q32 Q33 Q36 Q37 Q41 Q42: library part CMP-0000362-2, "Transistor, PNP, 60 V, 0.6 A, AEC-Q101, SOT-523", Manufacturer="Diodes Inc.", Supplier Part Number 1=MMBT2907AT-FDICT-ND, Value1="0.6 A", Value2=300
Q3 Q5 Q8 Q9 Q12 Q13 Q16 Q17 Q19 Q21 Q24 Q26 Q29 Q30 Q34 Q35 Q38 Q39 Q43 Q44: library part CMP-0000968-1, "MOSFET, N-CH, 100 V, 4.5 A, DQK0006C (WSON-6)", Alternate Manufacturer=None, Manufacturer="Texas Instruments"
Q22 Q31 Q40: library part CMP-0000485-2, "Bipolar (BJT) Transistor NPN 65V 100mA 100MHz 265mW Surface Mount SOT-723", Manufacturer="ON Semiconductor", Value1="0.1 A"
R1: library part CMP-0026918-5, "RES, 3.3 k, 5%, 0.063 W, AEC-Q200 Grade 0, 0402", Manufacturer=Vishay-Dale, Power_W=63mW, Supplier Part Number 1=541-3.3KJCT-ND, TempCo="200 ppm/C", Tolerance_%=5%, Value2=0.063W, Value_Code=3k30, ValueDisplayed=3.3k
R2 R4 R8 R9 R10 R11 R12 R13 R14 R15 R24 R25 R26 R38 R40 R50 R51 R62 R64 R75 R76 R88 R89: library part CMP-0027004-2, "RES, 0, 5%, 0.063 W, 0402", Manufacturer="Yageo America", Power_W=63mW, Supplier Part Number 1=311-0.0JRCT-ND, TempCo="200 ppm/C", Tolerance_%=5%, Value2=0.063W, Value_Code=0000, ValueDisplayed=0
R3 R5 R6 R32 R33 R39 R42 R44 R45 R52 R53 R56 R57 R63 R67 R69 R70 R77 R78 R82 R83 R90 R91: library part CMP-0026754-1, "RES, 10.0 k, 1%, 0.063 W, AEC-Q200 Grade 0, 0402", Manufacturer="Stackpole Electronics Inc", Power_W=63mW, Supplier Part Number 1=RMCF0402FT10K0CT-ND, TempCo="100 ppm/C", Tolerance_%=1%, Value2=0.063W, Value_Code=10k0, ValueDisplayed=10.0k
R7: library part CMP-0026722-1, "RES, 100, 1%, 0.063 W, 0402", Manufacturer="Yageo America", Power_W=63mW, Supplier Part Number 1=311-100LRCT-ND, TempCo="100 ppm/C", Tolerance_%=1%, Value2=0.063W, Value_Code=100R, ValueDisplayed=100
R16: library part CMP-0026243-2, "RES, 2.87 k, 1%, 0.063 W, AEC-Q200 Grade 0, 0402", Manufacturer=Vishay-Dale, Power_W=63mW, Supplier Part Number 1=541-2.87KLCT-ND, TempCo="100 ppm/C", Tolerance_%=1%, Value2=0.063W, Value_Code=2k87, ValueDisplayed=2.87k
R17: library part CMP-0026555-2, "RES, 7.50 k, 1%, 0.063 W, AEC-Q200 Grade 0, 0402", Manufacturer=Vishay-Dale, Power_W=63mW, Supplier Part Number 1=541-7.50KLCT-ND, TempCo="100 ppm/C", Tolerance_%=1%, Value2=0.063W, Value_Code=7k50, ValueDisplayed=7.50k
R18 R19 R20 R21 R22 R23 R28 R29 R30 R31 R35 R37 R41 R43 R48 R49 R54 R55 R59 R61 R65 R66 R68 R73 R74 R79 R80 R81 R86 R87 R92 R93 R94: library part CMP-0026659-1, "RES, 100 k, 1%, 0.1 W, 0402", Manufacturer=Panasonic, Power_W=100mW, TempCo="100 ppm/C", Tolerance_%=1%, Value2=0.1W, Value_Code=100k
R27: library part CMP-0026739-1, "RES, 4.70 k, 1%, 0.0625 W, 0402", Manufacturer="Yageo America", Power_W=62.5mW, Supplier Part Number 1=311-4.7KLRCT-ND, TempCo="100 ppm/C", Tolerance_%=1%, Value2=0.0625W, Value_Code=4k70, ValueDisplayed=4.70k
R34 R36 R46 R47 R58 R60 R71 R72 R84 R85: library part CMP-0026394-2, "RES, 475, 1%, 0.063 W, AEC-Q200 Grade 0, 0402", Manufacturer=Vishay-Dale, Power_W=63mW, Supplier Part Number 1=541-475LCT-ND, TempCo="100 ppm/C", Tolerance_%=1%, Value2=0.063W, Value_Code=475R, ValueDisplayed=475
U1: library part CMP-0013427-7, "500mA LDO, DRV0006A (WSON-6)", Alternate Manufacturer="Texas Instruments"
U2: library part CMP-0051718-3, "Single Power Supply BUFFER Logic Level Shifter (no enable), DCK0005A (SOT-SC70-5)", F @ Nom Voltage(Max)(Mhz)=50, Generic Part Number=SN74LV1T34, ICC @ Nom Voltage(Max)(mA)=0.01, Manufacturer="Texas Instruments", Operating Temperature Range(C)="-40 to 125", Rating=Catalog, tpd @ Nom Voltage(Max)(ns)=14.5,9.5,8.0,6.5, Voltage(Nom)(V)=1.8,2.5,3.3,5.5
U3: library part CMP-0074892-1, "100-mA, 30-V, Fixed-Output, Linear-Voltage Regulator, DBZ0003A (SOT-23-3)", Alternate Manufacturer="Texas Instruments", Alternate PartNumber=TLV76050DBZT
U4: library part CMP-0860872-1, "High-speed, robust EMC six-channel digital isolator, DBQ0016A (SSOP-16)", Alternate Manufacturer="Texas Instruments", Alternate PartNumber=ISO7760FDBQ, Operating Temperature Range="-55 to 125 C", Rating=Catalog
U5: library part CMP-0065673-1, "2.1-MHz, 250-uA, Low-Power Timer, D0008A (SOIC-8)", Alternate Manufacturer="Texas Instruments", PartNumber=TLC555ID
U6: library part CMP-0033666-1, "7-Channel Low Side Driver, 0 to 40 V VOUT, -40 to 125 degC, 16-Pin TSSOP (PW), RoHS, Tape and Reel", PartNumber=TPL7407LA, Temperature Max="125 degC", Temperature Min="-40 degC"
U7: library part CMP-0084705-1, "High-Speed, Low-Power, Robust EMC Quad-Channel Digital Isolator, DBQ0016A (SSOP-16)", Alternate Manufacturer="Texas Instruments", Alternate PartNumber=ISO7740FDBQ, Operating Temperature Range="-55 to 125 C", Rating=Catalog
ZZ1: library part AssemblyNoteLabel, Alternate Manufacturer=-
ZZ2 ZZ3 ZZ4: library part AssemblyNote, Alternate Manufacturer=-

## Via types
v1: diameter 24, hole 12, Top Layer to Bottom Layer, tented both sides, 144 vias
v2: diameter 40, hole 20, Top Layer to Bottom Layer, 10 vias
v3: diameter 19.68, hole 7.87, Top Layer to Bottom Layer, 2 vias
